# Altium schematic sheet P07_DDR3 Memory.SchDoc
size 386 x 246 mm
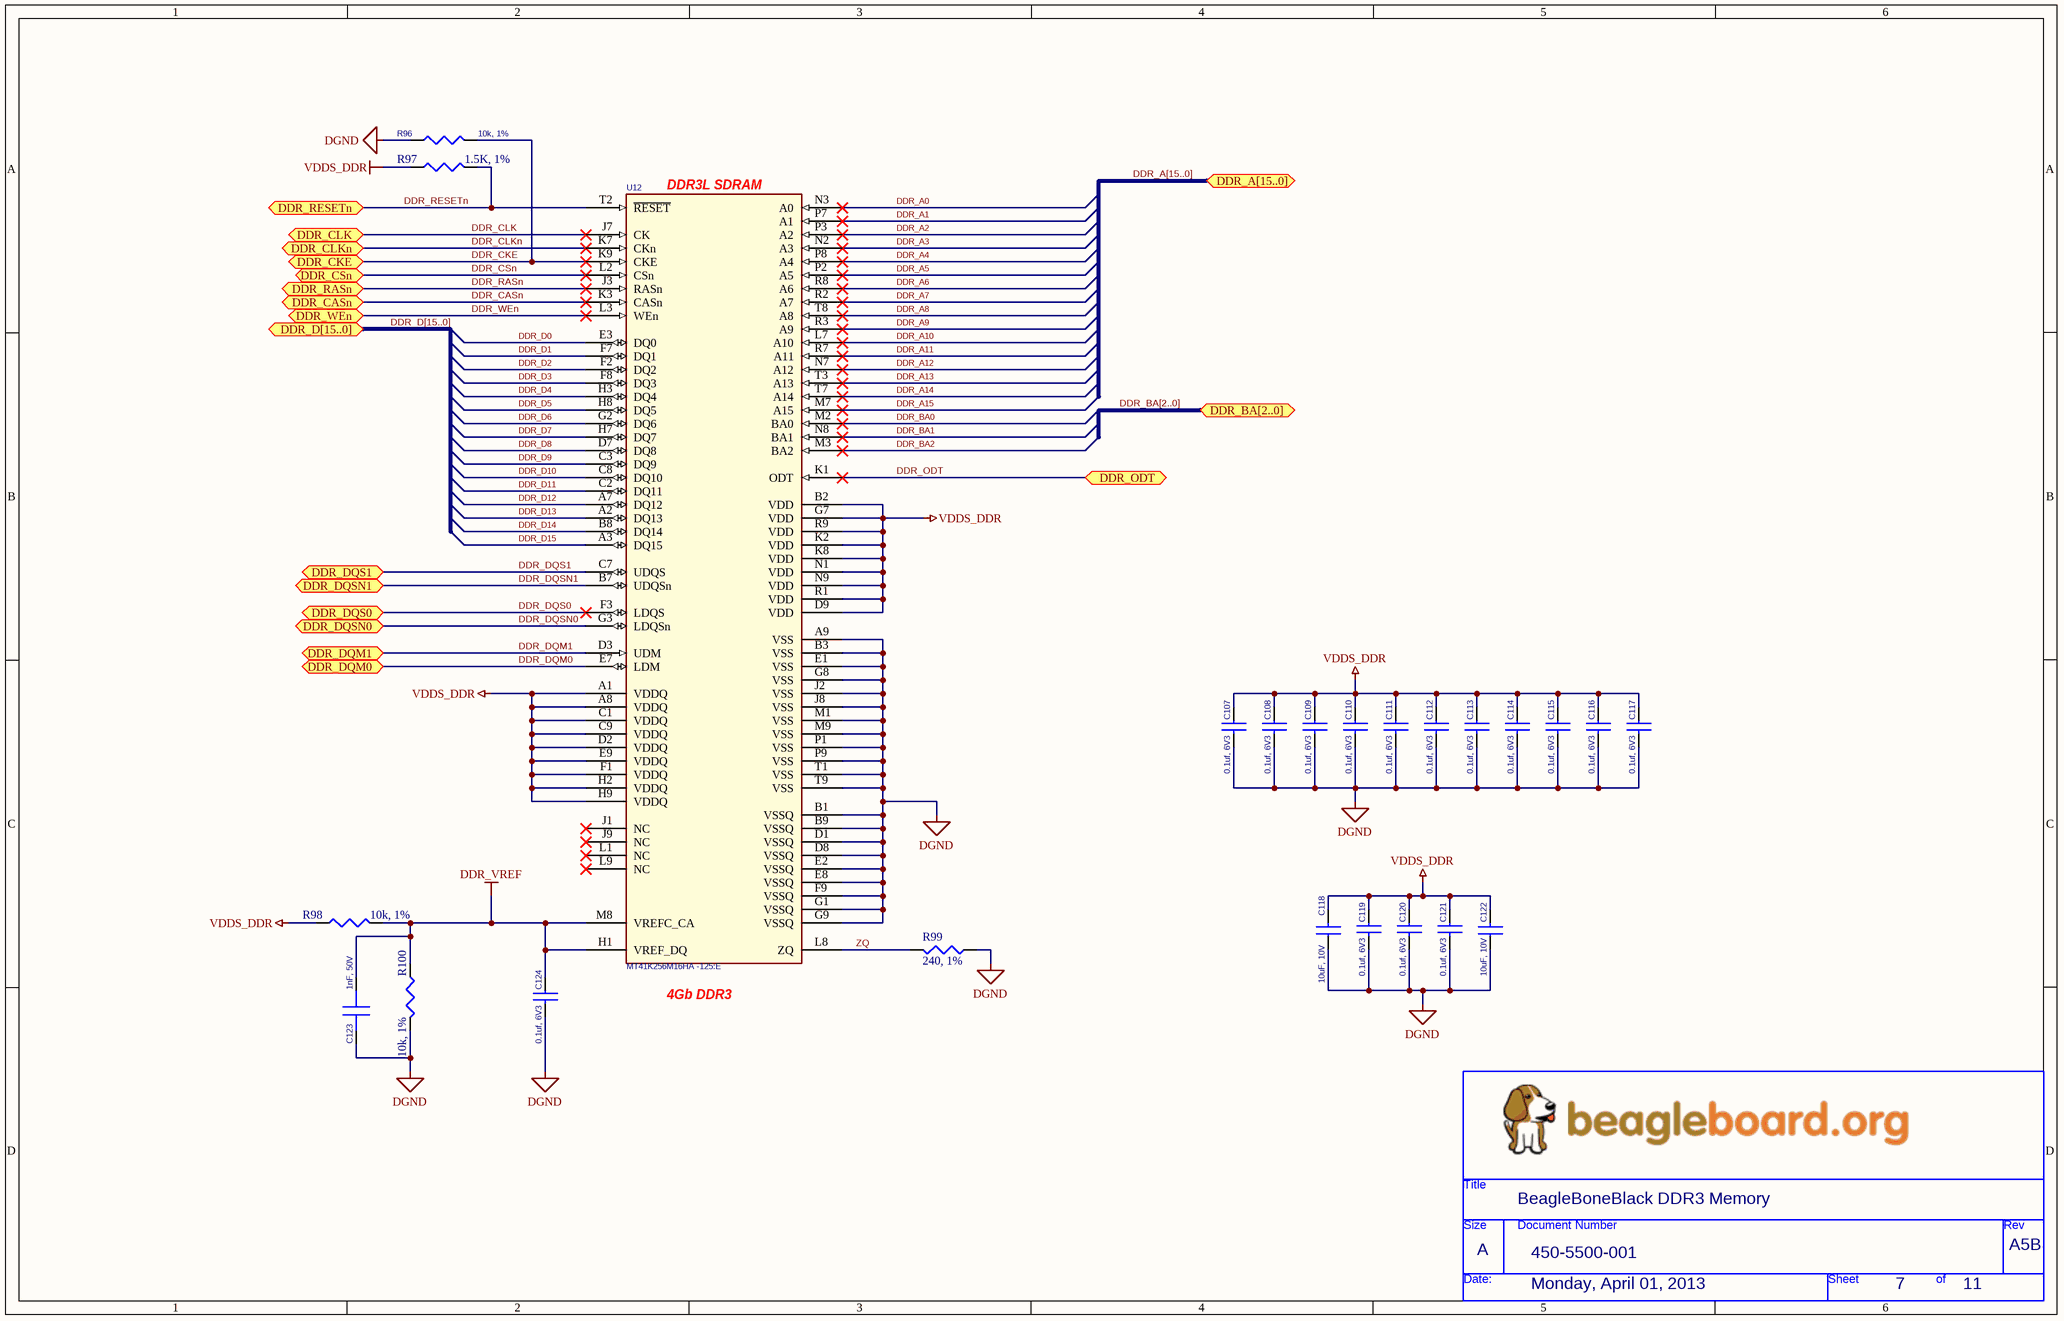
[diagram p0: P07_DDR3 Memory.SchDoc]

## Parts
*  Page Create Date: Monday, April 01, 2013  Doc: 450-5500-001  RevCode: A5B  Title: BeagleBoneBlack DDR3 Memory  Page Size: A  Page Number: 7  Page Count: 11  (hidden comment: BeagleBoard_org)  (graphical)
C107  0.1uf, 6V3  [402]
C108  0.1uf, 6V3  [402]
C109  0.1uf, 6V3  [402]
C110  0.1uf, 6V3  [402]
C111  0.1uf, 6V3  [402]
C112  0.1uf, 6V3  [402]
C113  0.1uf, 6V3  [402]
C114  0.1uf, 6V3  [402]
C115  0.1uf, 6V3  [402]
C116  0.1uf, 6V3  [402]
C117  0.1uf, 6V3  [402]
C118  10uF, 10V  [805]
C119  0.1uf, 6V3  [402]
C120  0.1uf, 6V3  [402]
C121  0.1uf, 6V3  [402]
C122  10uF, 10V  [805]
C123  1nF, 50V  [402]
C124  0.1uf, 6V3  [402]
R96  10k, 1%  [402]
R97  1.5K, 1%  [402]
R98  10k, 1%  [402]
R99  240, 1%  [402]
R100  10k, 1%  [402]
U12  MT41K256M16HA -125:E  [BGA96_T9_P8_9X14]

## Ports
DDR_A[15..0], DDR_BA[2..0], DDR_CASn, DDR_CKE, DDR_CLK, DDR_CLKn, DDR_CSn, DDR_D[15..0], DDR_DQM0, DDR_DQM1, DDR_DQS0, DDR_DQS1, DDR_DQSN0, DDR_DQSN1, DDR_ODT, DDR_RASn, DDR_RESETn, DDR_WEn

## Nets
DDR_VREF: C123.1 C124.1 R98.2 R100.1 U12.H1(VREF_DQ) U12.M8(VREFC_CA)
DGND: C107.2 C108.2 C109.2 C110.2 C111.2 C112.2 C113.2 C114.2 C115.2 C116.2 C117.2 C118.1 C119.2 C120.2 C121.2 C122.1 C123.2 C124.2 R96.1 R99.1 R100.2 U12.A9(VSS) U12.B1(VSSQ) U12.B3(VSS) U12.B9(VSSQ) U12.D1(VSSQ) U12.D8(VSSQ) U12.E1(VSS) U12.E2(VSSQ) U12.E8(VSSQ) U12.F9(VSSQ) U12.G1(VSSQ) U12.G8(VSS) U12.G9(VSSQ) U12.J2(VSS) U12.J8(VSS) U12.M1(VSS) U12.M9(VSS) U12.P1(VSS) U12.P9(VSS) U12.T1(VSS) U12.T9(VSS)
VDDS_DDR: C107.1 C108.1 C109.1 C110.1 C111.1 C112.1 C113.1 C114.1 C115.1 C116.1 C117.1 C118.2 C119.1 C120.1 C121.1 C122.2 R97.1 R98.1 U12.A1(VDDQ) U12.A8(VDDQ) U12.B2(VDD) U12.C1(VDDQ) U12.C9(VDDQ) U12.D2(VDDQ) U12.D9(VDD) U12.E9(VDDQ) U12.F1(VDDQ) U12.G7(VDD) U12.H2(VDDQ) U12.H9(VDDQ) U12.K2(VDD) U12.K8(VDD) U12.N1(VDD) U12.N9(VDD) U12.R1(VDD) U12.R9(VDD)
DDR_A0: U12.N3(A0)
DDR_A1: U12.P7(A1)
DDR_A2: U12.P3(A2)
DDR_A3: U12.N2(A3)
DDR_A4: U12.P8(A4)
DDR_A5: U12.P2(A5)
DDR_A6: U12.R8(A6)
DDR_A7: U12.R2(A7)
DDR_A8: U12.T8(A8)
DDR_A9: U12.R3(A9)
DDR_A10: U12.L7(A10)
DDR_A11: U12.R7(A11)
DDR_A12: U12.N7(A12)
DDR_A13: U12.T3(A13)
DDR_A14: U12.T7(A14)
DDR_A15: U12.M7(A15)
DDR_BA0: U12.M2(BA0)
DDR_BA1: U12.N8(BA1)
DDR_BA2: U12.M3(BA2)
DDR_CASn: U12.K3(CASn) ; port DDR_CASn
DDR_CKE: R96.2 U12.K9(CKE) ; port DDR_CKE
DDR_CLK: U12.J7(CK) ; port DDR_CLK
DDR_CLKn: U12.K7(CKn) ; port DDR_CLKn
DDR_CSn: U12.L2(CSn) ; port DDR_CSn
DDR_D0: U12.E3(DQ0)
DDR_D1: U12.F7(DQ1)
DDR_D2: U12.F2(DQ2)
DDR_D3: U12.F8(DQ3)
DDR_D4: U12.H3(DQ4)
DDR_D5: U12.H8(DQ5)
DDR_D6: U12.G2(DQ6)
DDR_D7: U12.H7(DQ7)
DDR_D8: U12.D7(DQ8)
DDR_D9: U12.C3(DQ9)
DDR_D10: U12.C8(DQ10)
DDR_D11: U12.C2(DQ11)
DDR_D12: U12.A7(DQ12)
DDR_D13: U12.A2(DQ13)
DDR_D14: U12.B8(DQ14)
DDR_D15: U12.A3(DQ15)
DDR_DQM0: U12.E7(LDM) ; port DDR_DQM0
DDR_DQM1: U12.D3(UDM) ; port DDR_DQM1
DDR_DQS0: U12.F3(LDQS) ; port DDR_DQS0
DDR_DQS1: U12.C7(UDQS) ; port DDR_DQS1
DDR_DQSN0: U12.G3(LDQSn) ; port DDR_DQSN0
DDR_DQSN1: U12.B7(UDQSn) ; port DDR_DQSN1
DDR_ODT: U12.K1(ODT) ; port DDR_ODT
DDR_RASn: U12.J3(RASn) ; port DDR_RASn
DDR_RESETn: R97.2 U12.T2(~{RESET}) ; port DDR_RESETn
DDR_WEn: U12.L3(WEn) ; port DDR_WEn
ZQ: R99.2 U12.L8(ZQ)

Not connected (* = marked no-connect by the designer): U12 J1(NC)* J9(NC)* L1(NC)* L9(NC)*

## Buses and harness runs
bus DDR_A[15..0] = port DDR_A[15..0]
bus DDR_BA[2..0] = port DDR_BA[2..0]
bus DDR_D[15..0] = port DDR_D[15..0]

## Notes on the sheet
- (near U12) DDR3L SDRAM
- (near U12) 4Gb DDR3

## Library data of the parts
C107-C117 C119-C121 C124 = CAP_0.01uf_X7R_16V_10%_0402: CAP CER 0.1UF 6.3V 10% X5R 0402; Manufacturer: TDK Corporation; Manufacturer Part Number: C1005X5R0J104K050BA; Capacitance: 0.1µF
C118 C122 = CAP_4.7uF_X5R_6.3V_10%_0603: CAP CER 10UF 10V Y5V 0805; Manufacturer: TDK Corporation; Manufacturer Part Number: C2012Y5V1A106Z; Capacitance: 10µF; Tolerance: -20%, +80%; Temperature Coefficient: Y5V (F)
C123 = CAP SMD: CAP CER 1000PF 16V 10% X7R 0402; Manufacturer: Yageo; Manufacturer Part Number: CC0402KRX7R7BB102
R96 R98 R100 = RES_10K_1/16W_1%_0402: RES 10K OHM 1/16W 5% 0402 SMD; Manufacturer: Rohm Semiconductor; Manufacturer Part Number: MCR01MZPJ103; Power (Watts): 0.063W, 1/16W; Temperature Coefficient: ±200ppm/°C
R97 = RES_10K_1/16W_1%_0402: RES 1.50K OHM 1/16W 1% 0402 SMD; Manufacturer: Yageo; Manufacturer Part Number: RC0402FR-071K5L; Power (Watts): 0.063W, 1/16W; Temperature Coefficient: ±100ppm/°C
R99 = RES_10K_1/16W_1%_0402: RES 240 OHM 1/10W 5% 0402 SMD; Manufacturer: Yageo; Manufacturer Part Number: RC0402FR-07240RL; Resistance (Ohms): 240; Power (Watts): 0.063W, 1/16W; Temperature Coefficient: ±100ppm/°C
U12 = MT41K256M16HA: DDR2 SDRAM 2Gb (256Mx8); Manufacturer: Micron Technology; Lead Time: 0 weeks; Peak Solder Temperature: 260 deg C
